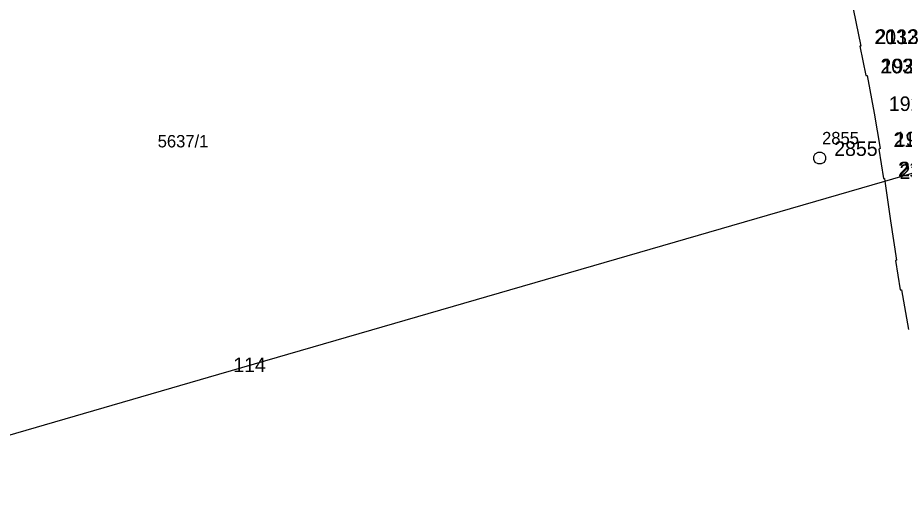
# Model space of a CAD drawing. Extents: x -822293 to -820259, y -1071573 to -1068794.
# Drawn here: x -821588.1 to -821466.4, y -1070159.3 to -1070094 of the extents above; entities that cross this region are included whole.
import ezdxf

# ---------------------------------------------------------------- set-up
doc = ezdxf.new("R2010")
doc.units = 0
for name, color, linetype in [('Vrstva 14', 7, 'Continuous'), ('Vrstva 16', 7, 'Continuous'), ('Vrstva 2', 7, 'Continuous'), ('Vrstva 3', 7, 'Continuous'), ('Vrstva 5', 7, 'Continuous'), ('Vrstva 8', 7, 'Continuous'), ('Vrstva 9', 7, 'Continuous')]:
    doc.layers.add(name, color=color, linetype=linetype)

# ---------------------------------------------------------------- blocks, each defined once
blk = doc.blocks.new('Z101')
at = {"layer": 'Vrstva 2'}
for p, q in [((-80, 20), (-60, 60)), ((-80, -20), (-80, 20)), ((-60, 60), (-20, 80)), ((-20, 80), (20, 80)), ((0, 0), (0, 0)), ((20, 80), (60, 60)), ((60, 60), (80, 20)), ((80, 20), (80, -20)), ((-60, -60), (-80, -20)), ((-20, -80), (-60, -60)), ((20, -80), (-20, -80)), ((60, -60), (20, -80)), ((80, -20), (60, -60))]:
    blk.add_line(p, q, dxfattribs=at)

msp = doc.modelspace()

# ---------------------------------------------------------------- linework, layer by layer
at = {"layer": 'Vrstva 2'}
for p, q in [((-821469.07, -1070116.41), (-821463.03, -1070114.66)), ((-821560.5, -1070142.95), (-821469.07, -1070116.41)), ((-821657.98, -1070171.24), (-821560.5, -1070142.95))]:
    msp.add_line(p, q, dxfattribs=at)
at = {"layer": 'Vrstva 3'}
for p, q in [((-821474.25, -1070088.76), (-821472.38, -1070097.86)), ((-821472.38, -1070097.86), (-821472.52, -1070097.89)), ((-821472.52, -1070097.89), (-821471.69, -1070101.91)), ((-821471.69, -1070101.91), (-821471.53, -1070101.9)), ((-821471.53, -1070101.9), (-821470.53, -1070107.08)), ((-821470.53, -1070107.08), (-821469.71, -1070111.94)), ((-821469.71, -1070111.94), (-821469.9, -1070112.02)), ((-821469.9, -1070112.02), (-821469.27, -1070116.07)), ((-821469.27, -1070116.07), (-821469.12, -1070116.05)), ((-821469.12, -1070116.05), (-821469.07, -1070116.41)), ((-821469.07, -1070116.41), (-821468.31, -1070121.86)), ((-821468.31, -1070121.86), (-821467.49, -1070127.26)), ((-821467.49, -1070127.26), (-821467.63, -1070127.31)), ((-821467.63, -1070127.31), (-821466.96, -1070131.36)), ((-821466.96, -1070131.36), (-821466.81, -1070131.34)), ((-821466.81, -1070131.34), (-821465.85, -1070136.8))]:
    msp.add_line(p, q, dxfattribs=at)
at = {"layer": 'Vrstva 8'}
for p, q in [((-821472.52, -1070097.89), (-821472.52, -1070097.89)), ((-821472.38, -1070097.86), (-821472.38, -1070097.86)), ((-821471.69, -1070101.91), (-821471.69, -1070101.91)), ((-821471.53, -1070101.9), (-821471.53, -1070101.9)), ((-821470.53, -1070107.08), (-821470.53, -1070107.08)), ((-821469.9, -1070112.02), (-821469.9, -1070112.02)), ((-821469.71, -1070111.94), (-821469.71, -1070111.94)), ((-821478.03, -1070113.25), (-821478.03, -1070113.25)), ((-821469.27, -1070116.07), (-821469.27, -1070116.07)), ((-821469.12, -1070116.05), (-821469.12, -1070116.05)), ((-821469.07, -1070116.41), (-821469.07, -1070116.41)), ((-821468.31, -1070121.86), (-821468.31, -1070121.86)), ((-821467.49, -1070127.26), (-821467.49, -1070127.26)), ((-821467.63, -1070127.31), (-821467.63, -1070127.31)), ((-821466.96, -1070131.36), (-821466.96, -1070131.36)), ((-821466.81, -1070131.34), (-821466.81, -1070131.34)), ((-821560.5, -1070142.95), (-821560.5, -1070142.95))]:
    msp.add_line(p, q, dxfattribs=at)

# ---------------------------------------------------------------- block references
at = {"layer": 'Vrstva 14', "xscale": 0.01, "yscale": 0.01}
msp.add_blockref('Z101', (-821478.03, -1070113.25), dxfattribs=at)

# ---------------------------------------------------------------- texts
at = {"layer": 'Vrstva 16'}
msp.add_text('2855', height=1.7, dxfattribs=at).set_placement((-821477.7, -1070111.35))
at = {"layer": 'Vrstva 5'}
msp.add_text('5637/1', height=1.7, dxfattribs=at).set_placement((-821568.873, -1070111.78))
at = {"layer": 'Vrstva 9'}
for s, p in [('2032', (-821470.52, -1070097.59)), ('2113', (-821470.38, -1070097.56)), ('2031', (-821469.69, -1070101.61)), ('1923', (-821469.53, -1070101.6)), ('1922', (-821468.53, -1070106.78)), ('2120', (-821467.9, -1070111.72)), ('1921', (-821467.71, -1070111.64)), ('2855', (-821476.03, -1070112.95)), ('2121', (-821467.27, -1070115.77)), ('2122', (-821467.12, -1070115.75)), ('2374', (-821467.07, -1070116.11)), ('114', (-821558.5, -1070142.65))]:
    msp.add_text(s, height=2, dxfattribs=at).set_placement(p)

doc.saveas('drawing.dxf')
